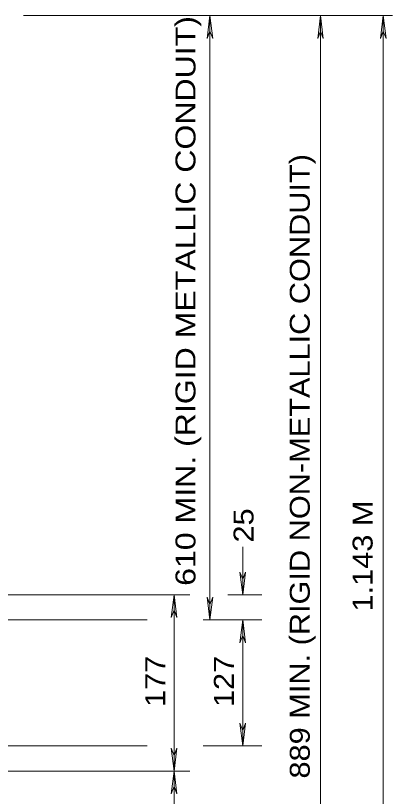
# Model space of a CAD drawing. Extents: x 312583 to 312854, y 144419 to 144597.
# Drawn here: x 312669.93 to 312684.27, y 144464.5 to 144494.21 of the extents above; entities that cross this region are included whole.
import ezdxf

# ---------------------------------------------------------------- set-up
doc = ezdxf.new("R2010")
doc.units = 0
doc.header["$LTSCALE"] = 0.3
doc.layers.add('2', color=7, linetype='Continuous', lineweight=13)

msp = doc.modelspace()

# ---------------------------------------------------------------- linework, layer by layer
at = {"layer": '2'}
for p, q in [((312670.2331, 144494.2114), (312684.2708, 144494.2114)), ((312677.3248, 144494.2114), (312677.2175, 144493.3451)), ((312677.3248, 144471.2114), (312677.3248, 144494.2114)), ((312677.3248, 144494.2114), (312677.4321, 144493.3451)), ((312681.5338, 144494.2114), (312681.4265, 144493.3451)), ((312681.5338, 144460.6698), (312681.5338, 144494.2114)), ((312681.5338, 144494.2114), (312681.6411, 144493.3451)), ((312683.9258, 144494.2114), (312683.8185, 144493.3451)), ((312683.9258, 144451.0864), (312683.9258, 144494.2114)), ((312683.9258, 144494.2114), (312684.0331, 144493.3451)), ((312677.2175, 144493.3451), (312677.3248, 144493.6211)), ((312677.4321, 144493.3451), (312677.3248, 144493.6211)), ((312681.4265, 144493.3451), (312681.5338, 144493.6211)), ((312681.6411, 144493.3451), (312681.5338, 144493.6211)), ((312683.8185, 144493.3451), (312683.9258, 144493.6211)), ((312684.0331, 144493.3451), (312683.9258, 144493.6211)), ((312678.5745, 144472.1698), (312678.5745, 144473.9944)), ((312678.4671, 144473.0361), (312678.5745, 144472.7601)), ((312678.5745, 144472.1698), (312678.4671, 144473.0361)), ((312678.6818, 144473.0361), (312678.5745, 144472.7601)), ((312678.5745, 144472.1698), (312678.6818, 144473.0361)), ((312665.5258, 144472.1698), (312676.5581, 144472.1698)), ((312675.9601, 144472.1698), (312675.8528, 144471.3034)), ((312675.9601, 144465.4614), (312675.9601, 144472.1698)), ((312675.9601, 144472.1698), (312676.0675, 144471.3034)), ((312678.0071, 144472.1698), (312679.2951, 144472.1698)), ((312677.2175, 144472.0778), (312677.3248, 144471.8018)), ((312677.3248, 144471.2114), (312677.2175, 144472.0778)), ((312677.4321, 144472.0778), (312677.3248, 144471.8018)), ((312677.3248, 144471.2114), (312677.4321, 144472.0778)), ((312675.8528, 144471.3034), (312675.9601, 144471.5794)), ((312676.0675, 144471.3034), (312675.9601, 144471.5794)), ((312667.2355, 144471.2114), (312674.9328, 144471.2114)), ((312677.0718, 144471.2114), (312679.2951, 144471.2114)), ((312678.5745, 144471.2114), (312678.4671, 144470.3451)), ((312678.5745, 144466.4198), (312678.5745, 144471.2114)), ((312678.5745, 144471.2114), (312678.6818, 144470.3451)), ((312678.4671, 144470.3451), (312678.5745, 144470.6211)), ((312678.6818, 144470.3451), (312678.5745, 144470.6211)), ((312678.4671, 144467.2861), (312678.5745, 144467.0101)), ((312678.5745, 144466.4198), (312678.4671, 144467.2861)), ((312678.6818, 144467.2861), (312678.5745, 144467.0101)), ((312678.5745, 144466.4198), (312678.6818, 144467.2861)), ((312667.2355, 144466.4198), (312674.9328, 144466.4198)), ((312675.8528, 144466.3278), (312675.9601, 144466.0518)), ((312675.9601, 144465.4614), (312675.8528, 144466.3278)), ((312676.0675, 144466.3278), (312675.9601, 144466.0518)), ((312675.9601, 144465.4614), (312676.0675, 144466.3278)), ((312677.0718, 144466.4198), (312679.2951, 144466.4198)), ((312665.5258, 144465.4614), (312676.5581, 144465.4614)), ((312675.9601, 144465.4614), (312675.8528, 144464.5951)), ((312675.9601, 144465.4614), (312675.9601, 144461.7431)), ((312675.9601, 144465.4614), (312676.0675, 144464.5951)), ((312675.8528, 144464.5951), (312675.9601, 144464.8711)), ((312676.0675, 144464.5951), (312675.9601, 144464.8711))]:
    msp.add_line(p, q, dxfattribs=at)

# ---------------------------------------------------------------- texts
for s, width, p in [('610 MIN. (RIGID METALLIC CONDUIT)', 1.2, (312676.7743, 144472.5102)), ('889 MIN. (RIGID NON-METALLIC CONDUIT)', 1.15, (312681.1251, 144465.177)), ('1.143 M', 1.15, (312683.5171, 144471.5345)), ('25 ', 1.15, (312678.9839, 144474.1582)), ('177 ', 1.15, (312675.6223, 144467.8965)), ('127 ', 1.15, (312678.2367, 144467.8965))]:
    msp.add_text(s, height=0.76, rotation=90, dxfattribs=dict(at, width=width)).set_placement(p)

doc.saveas('drawing.dxf')
